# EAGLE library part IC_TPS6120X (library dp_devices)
Low input voltage Synchronous Boost converter
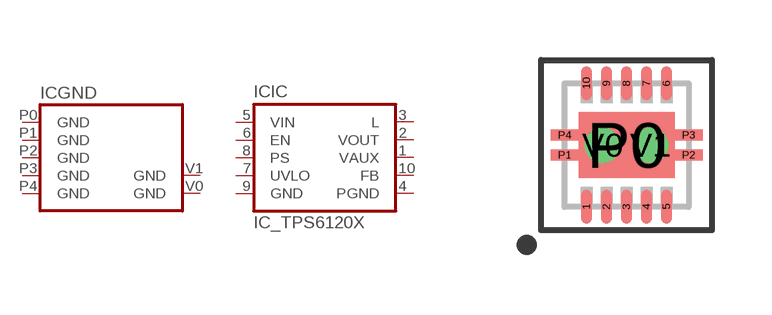
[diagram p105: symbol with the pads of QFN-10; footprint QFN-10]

Designator prefix IC; gates IC=TPS6120X GND=QFN-10-GND

## IC_TPS6120X-QFN10  [QFN-10]
1  IC:VAUX
2  IC:VOUT  out
3  IC:L  in
4  IC:PGND  sup
5  IC:VIN  in
6  IC:EN  in
7  IC:UVLO  in
8  IC:PS  in
9  IC:GND  sup
10  IC:FB  in
P0  GND:GND  sup
P1  GND:GND  sup
P2  GND:GND  sup
P3  GND:GND  sup
P4  GND:GND  sup
V0  GND:GND  sup
V1  GND:GND  sup

## Footprint QFN-10 (pad centres in mm)
10 pins Quad Flat Leadless Size: 3 x 3 mm Pads: 0.85 x 0.28 mm pads Pin Pitch: 0.5mm pitch
smd 0.28 x 0.85: 1 -1,-1.545; 2 -0.5,-1.545; 3 0,-1.545; 4 0.5,-1.545; 5 1,-1.545; 6 1,1.545; 7 0.5,1.545; 8 0,1.545; 9 -0.5,1.545; 10 -1,1.545
smd 2.4 x 1.65: P0 0,0
smd 0.7 x 0.28: P1 -1.55,-0.25; P2 1.55,-0.25; P3 1.55,0.25; P4 -1.55,0.25
drill 0.381 round: V0 -0.6,0; V1 0.6,0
